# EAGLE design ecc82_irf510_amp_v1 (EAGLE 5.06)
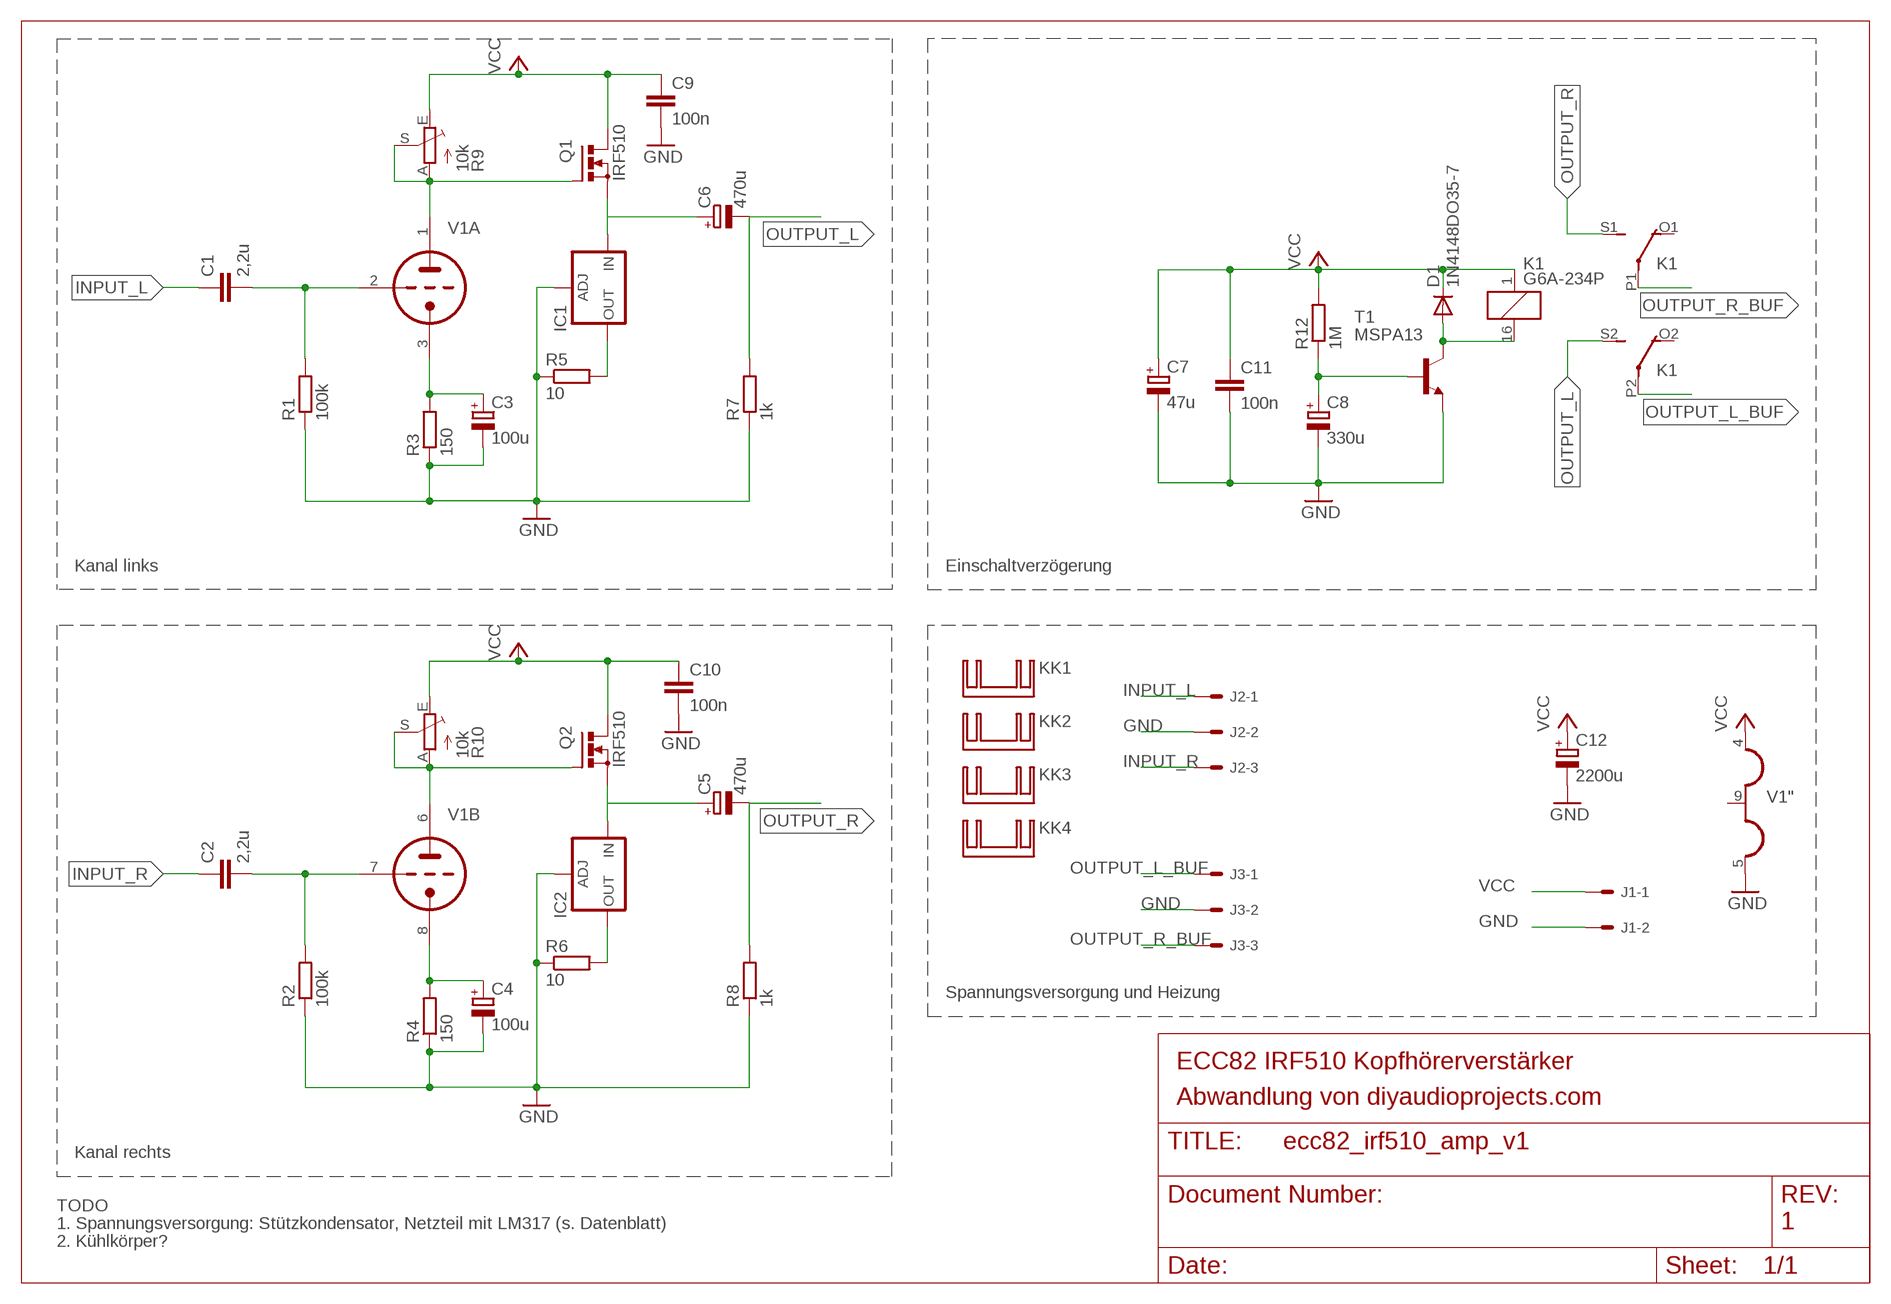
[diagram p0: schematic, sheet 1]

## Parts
C1  2,2u  C10/6  [C10B6]
C2  2,2u  C10/6  [C10B6]
C3  100u  CPOL-EUE5-8.5  [E5-8,5]
C4  100u  CPOL-EUE5-8.5  [E5-8,5]
C5  470u  CPOL-EUE5-10.5  [E5-10,5]
C6  470u  CPOL-EUE5-10.5  [E5-10,5]
C7  47u  CPOL-EUE2-5  [E2-5]
C8  330u  CPOL-EUE5-10.5  [E5-10,5]
C9  100n  C-EUC0805  [C0805]
C10  100n  C-EUC0805  [C0805]
C11  100n  C-EUC0805  [C0805]
C12  2200u  CPOL-EUE5-13  [E5-13]
D1  1N4148DO35-7  [DO35-7]
IC1  LM317TS  [317TS]
IC2  LM317TS  [317TS]
J1  22-27-2021-02  [6410-02]
J2  22-27-2031-03  [6410-03]
J3  22-27-2031-03  [6410-03]
K1  G6A-234P  [G6A-234P]
KK1  D03S  [D03S]
KK2  D03S  [D03S]
KK3  D03S  [D03S]
KK4  D03S  [D03S]
Q1  IRF510  IRF512  [TO220BV]
Q2  IRF510  IRF512  [TO220BV]
R1  100k  R-EU_0207/10  [0207/10]
R2  100k  R-EU_0207/10  [0207/10]
R3  150  R-EU_0207/10  [0207/10]
R4  150  R-EU_0207/10  [0207/10]
R5  10  R-EU_0207/10  [0207/10]
R6  10  R-EU_0207/10  [0207/10]
R7  1k  R-EU_0207/10  [0207/10]
R8  1k  R-EU_0207/10  [0207/10]
R9  10k  TRIM_EU-B64Y  [B64Y]
R10  10k  TRIM_EU-B64Y  [B64Y]
R12  1M  R-EU_0207/10  [0207/10]
T1  MSPA13  MPSA13-NPN-TO92-CBE  [TO92-CBE]
V1  ECC82-P  [NOVAL]

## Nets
GND: C3.- C4.- C7.- C8.- C9.2 C10.2 C11.2 C12.- IC1.1(ADJ) IC2.1(ADJ) J1.2 J2.2 J3.2 R1.1 R2.1 R3.1 R4.1 R5.1 R6.1 R7.1 R8.1 T1.E V1.5(":H3)
INPUT_L: C1.1 J2.1
INPUT_R: C2.1 J2.3
N$1: C1.2 R1.2 V1.2(A:TG)
N$2: C3.+ R3.2 V1.3(A:TK)
N$3: Q1.G R9.A R9.S V1.1(A:TA)
N$4: C2.2 R2.2 V1.7(B:TG)
N$5: C4.+ R4.2 V1.8(B:TK)
N$6: Q2.G R10.A R10.S V1.6(B:TA)
N$7: C6.+ IC1.3(IN) Q1.S
N$8: IC1.2(OUT) R5.2
N$9: C5.+ IC2.3(IN) Q2.S
N$10: IC2.2(OUT) R6.2
N$12: D1.A K1.16 T1.C
N$13: C8.+ R12.1 T1.B
OUTPUT_L: C6.- K1.S2(3:S) R7.2
OUTPUT_L_BUF: J3.1 K1.P2(3:P)
OUTPUT_R: C5.- K1.S1(2:S) R8.2
OUTPUT_R_BUF: J3.3 K1.P1(2:P)
VCC: C7.+ C9.1 C10.1 C11.1 C12.+ D1.C J1.1 K1.1 Q1.D Q2.D R9.E R10.E R12.2 V1.4(":H1)
Unconnected: K1.O1(2:O) K1.O2(3:O) V1.9(":H2)

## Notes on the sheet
- Kanal links | Einschaltverzögerung
- Spannungsversorgung und Heizung
- ECC82 IRF510 Kopfhörerverstärker
- Abwandlung von diyaudioprojects.com
- Kanal rechts
- TODO
- 1. Spannungsversorgung: Stützkondensator, Netzteil mit LM317 (s. Datenblatt) | 1
- 2. Kühlkörper?

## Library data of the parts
C1 C2 = capacitor-wima:C: CAPACITOR
C3-C8 C12 = rcl:CPOL-EU: POLARIZED CAPACITOR, European symbol
C9-C11 = rcl:C-EU: CAPACITOR, European symbol
D1 = diode:1N4148: DIODE
IC1 IC2 = v-reg:LM317TS: VOLTAGE REGULATOR
J1 = con-molex:22-?-02: CONNECTOR
J2 J3 = con-molex:22-?-03: CONNECTOR wire to board 2.54 mm (.1 inch) pitch header
K1 = relay:G6A-234P: RELAY 2 x switch, 0.3 A/125 V AC, 1 A/30 V DC, Omron
KK1-KK4 = heatsink:D03S: HEATSINK
Q1 Q2 = transistor-power:IRF512: N-CHANNEL MOS FET
R1-R8 R12 = rcl:R-EU_: RESISTOR, European symbol
R9 R10 = pot:TRIM_EU-: POTENTIOMETER
T1 = transistor:*-NPN-: NPN Transistror BF959 corrected 2008.03.06
V1 = tubes:ECC82-P

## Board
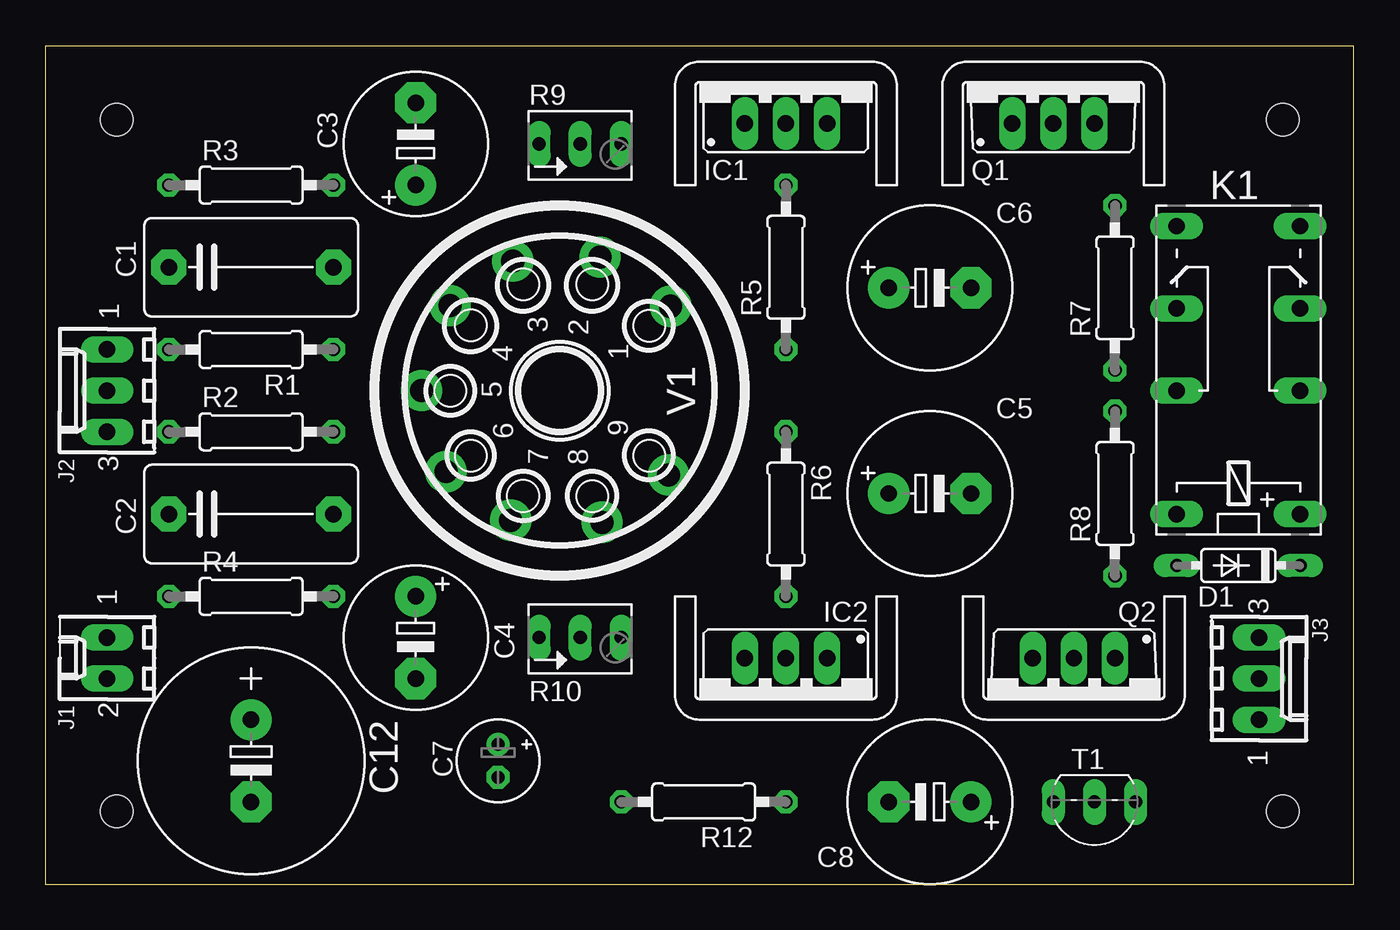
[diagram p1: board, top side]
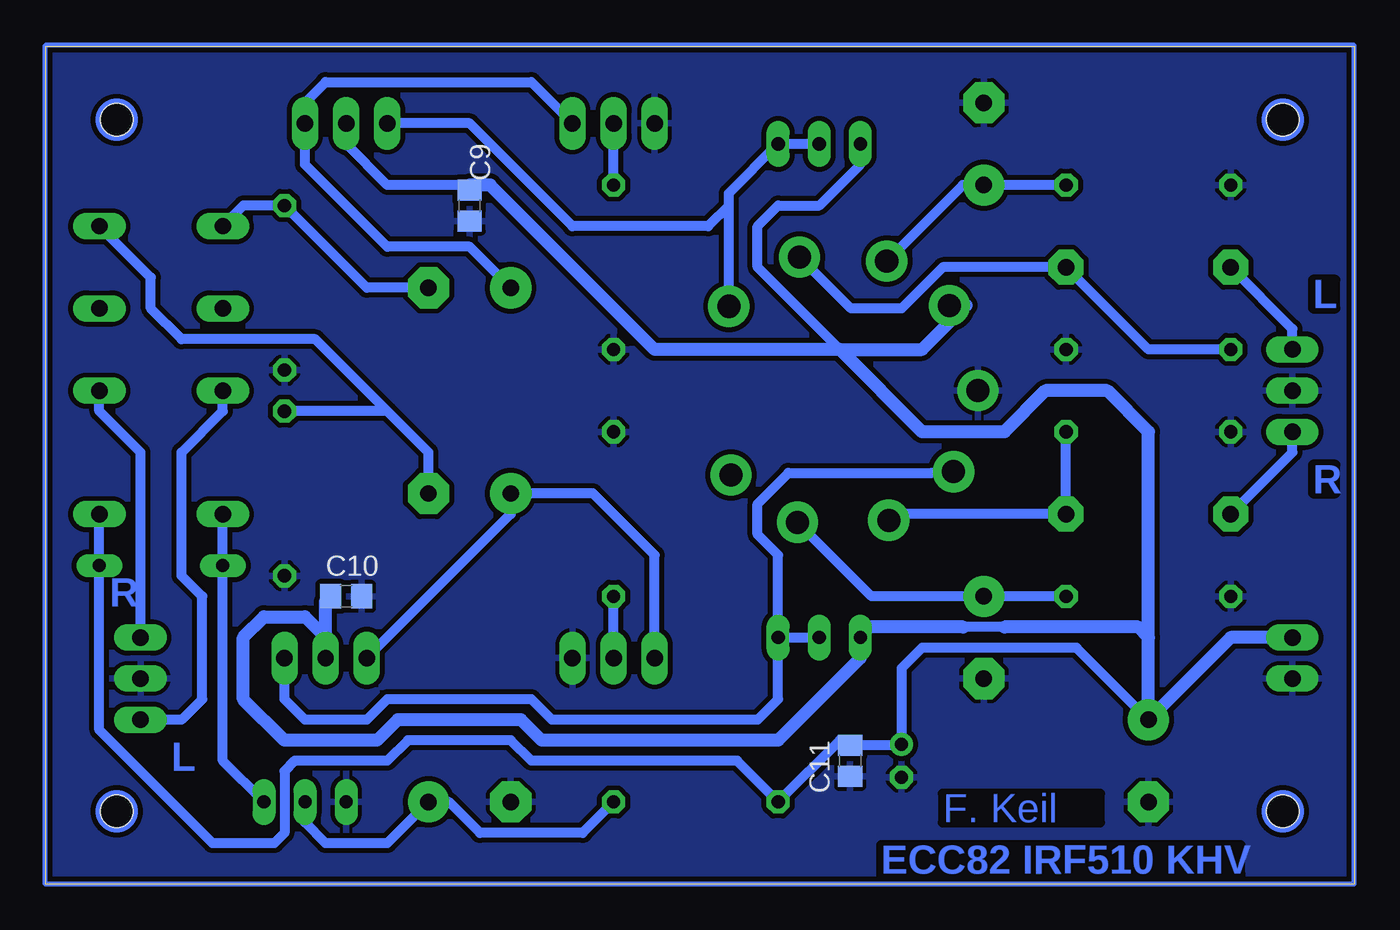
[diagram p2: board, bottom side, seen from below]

Size 80.79 x 51.76 mm. Coordinates in mm from the lower left corner, seen from the top.
Outline: 0,0 80.79,0 80.79,51.76 0,51.76 0,0
Copper layers (1*16): Top 0.035mm / dielectric 1.5mm / Bottom 0.035mm
Design rules "SparkFun *": minimum track width 8mil, minimum drill 20mil, track to track 10mil, track to pad 10mil, pad to pad 10mil, via to via 10mil, smd to smd 10mil, copper to edge 10mil, drill to drill 8mil, minimum pad ring 12mil, minimum via ring 10mil, stop-mask expansion 4mil, vias tented up to drill 25mil, thermal gap 10mil
Holes 2 mm at 4.4,4.5 4.4,47.2 76.4,4.5 76.4,47.2

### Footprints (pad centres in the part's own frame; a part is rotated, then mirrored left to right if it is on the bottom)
C10B6 = drill 1.016 pad 2.159 octagon: 1 -5.08,0; 2 5.08,0
E5-8,5 = drill 1.016 pad 2.54 round: + -2.54,0 | drill 1.016 pad 2.54 octagon: - 2.54,0
E5-10,5 = drill 1.016 pad 2.54 round: + -2.54,0 | drill 1.016 pad 2.54 octagon: - 2.54,0
E2-5 = drill 0.813 pad 1.27 round: + -1.016,0 | drill 0.813 pad 1.27 octagon: - 1.016,0
C0805 = smd 1.3 x 1.5: 1 -0.95,0; 2 0.95,0
E5-13 = drill 1.016 pad 2.54 round: + -2.54,0 | drill 1.016 pad 2.54 octagon: - 2.54,0
DO35-7 = drill 0.813 long: A 3.81,0; C -3.81,0
317TS = drill 1.016 long: 1 -2.54,-2.54; 2 0,-2.54; 3 2.54,-2.54
6410-02 = drill 1.016 long: 1 1.27,0; 2 -1.27,0
6410-03 = drill 1.016 long: 1 2.54,0; 2 0,0; 3 -2.54,0
G6A-234P = drill 1.016 long: 1 -3.81,-3.81; 16 -3.81,3.81; O1 8.89,-3.81; O2 8.89,3.81; P1 3.81,-3.81; P2 3.81,3.81; S1 13.97,-3.81; S2 13.97,3.81
TO220BV = drill 1.016 long: D 0,-2.54; G -2.54,-2.54; S 2.54,-2.54
0207/10 = drill 0.813 octagon: 1 -5.08,0; 2 5.08,0
B64Y = drill 0.813 long: A 2.54,0; E -2.54,0; S 0,0
TO92-CBE = drill 0.813 long: B 0,0; C -2.54,0; E 2.54,0
NOVAL = drill 1.422 pad 2.54 round: 1 5.207,-6.858; 2 8.254,-2.484; 3 8.004,2.893; 4 5.258,6.77; 5 0,8.524; 6 -5.004,7.024; 7 -8.004,3.02; 8 -8.127,-2.611; 9 -5.207,-6.731

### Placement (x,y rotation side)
C1  12.7,38.1 0 top
C2  12.7,22.86 0 top
C3  22.86,45.72 90 top
C4  22.86,15.24 270 top
C5  54.61,24.13 0 top
C6  54.61,36.83 0 top
C7  27.94,7.62 270 top
C8  54.61,5.08 180 top
C9  54.61,41.91 270 bottom
C10  62.23,17.78 0 bottom
C11  31.11,7.62 270 bottom
C12  12.7,7.62 270 top
D1  73.66,19.68 180 top
IC1  45.72,49.53 0 top
IC2  45.72,11.43 180 top
J1  3.81,13.97 90 top
J2  3.81,30.48 90 top
J3  74.93,12.7 270 top
K1  73.66,26.67 90 top
KK1  63.5,11.43 0 top
KK2  45.72,11.43 0 top
KK3  45.72,49.53 180 top
KK4  62.23,49.53 180 top
Q1  62.23,49.53 0 top
Q2  63.5,11.43 180 top
R1  12.7,33.02 180 top
R2  12.7,27.94 0 top
R3  12.7,43.18 0 top
R4  12.7,17.78 0 top
R5  45.72,38.1 90 top
R6  45.72,22.86 270 top
R7  66.04,36.83 90 top
R8  66.04,24.13 90 top
R9  33.02,45.72 0 top
R10  33.02,15.24 0 top
R12  40.64,5.08 180 top
T1  64.77,5.08 180 top
V1  31.75,30.48 90 top

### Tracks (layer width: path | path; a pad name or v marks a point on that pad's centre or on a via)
GND
  pour Bottom (isolate 0.305): 0,52.07 80.64,52.07 80.64,0 0,0
INPUT_L
  Bottom 0.61: J2.1 3.81,34.29 C1.1
INPUT_R
  Bottom 0.61: J2.3 3.81,26.67 C2.1
N$1
  Bottom 0.61: R1.2 12.7,33.02 C1.2 25.4,38.1 27.94,35.56 31.06,35.56 V1.2
N$2
  Bottom 0.61: R3.2 C3.+ 24.16,43.18 V1.3
N$3
  Bottom 0.61: R9.S R9.A 38.61,42.67 38.61,41.91 | V1.1 38.61,41.91 | Q1.G 54.61,46.99 48.26,40.64 39.88,40.64 38.61,41.91
N$4
  Bottom 0.61: V1.7 28.35,22.86 C2.2 R2.2
N$5
  Bottom 0.61: V1.8 29.79,17.78 C4.+ R4.2
N$6
  Bottom 0.61: R10.A R10.S | Q2.G 66.04,11.43 64.77,10.16 60.96,10.16 59.69,11.43 50.8,11.43 49.53,10.16 36.83,10.16 35.56,11.43 R10.A | R10.A 35.56,20.32 36.83,21.59 36.83,23.5 34.92,25.4 26.07,25.4 V1.6
N$7
  Bottom 0.61: C6.+ 54.61,39.37 59.69,39.37 64.77,44.45 Q1.S 64.77,48.26 63.5,49.53 50.8,49.53 IC1.3
N$8
  Bottom 0.61: R5.2 IC1.2
N$9
  Bottom 0.61: IC2.3 43.18,20.32 46.99,24.13 C5.+ 52.07,22.86 Q2.S
N$10
  Bottom 0.61: IC2.2 R6.2
N$11
  Bottom 0.305: 0,51.8 80.8,51.8 80.8,0 0,0 0,51.8
N$12
  Bottom 0.61: K1.16 D1.A 69.85,7.62 T1.C
N$13
  Bottom 0.61: R12.1 47.62,3.17 53.98,3.17 55.88,5.08 C8.+ 59.69,2.54 63.5,2.54 64.77,3.81 T1.B
OUTPUT_L
  Bottom 0.61: C6.- 60.96,36.83 R7.2 68.58,41.91 K1.S2
OUTPUT_L_BUF
  Bottom 0.61: K1.P2 69.85,29.21 72.39,26.67 72.39,19.05 71.12,17.78 71.12,11.43 72.39,10.16 J3.1
OUTPUT_R
  Bottom 0.61: K1.S1 74.3,37.47 74.3,35.56 72.39,33.66 64.14,33.66 59.69,29.21 | C5.- 57.15,26.67 59.69,29.21 | 59.69,29.21 R8.2
OUTPUT_R_BUF
  Bottom 0.61: K1.P1 77.47,29.21 74.93,26.67 J3.3
VCC
  Bottom 0.61: R9.E 30.48,44.45 33.02,41.91 35.56,41.91 36.83,40.64 36.83,38.1 31.75,33.02 | K1.1 D1.C 77.47,9.53 70.48,2.54 66.67,2.54 66.04,3.17 66.04,6.99 65.41,7.62 59.69,7.62 58.42,8.89 52.07,8.89 50.8,7.62 38.1,7.62 R12.2 31.75,8.89 31.43,8.89 C11.1 28.01,8.57 C7.+ 27.94,13.34 26.67,14.61 17.14,14.61 C12.+ | 54.61,43.18 59.69,43.18 62.23,45.72 | 21.59,15.88 24.13,15.88
  Bottom 0.813: 31.75,33.02 26.67,33.02 23.95,35.74 V1.4 | 62.23,45.72 Q1.D | 31.75,33.02 26.67,27.94 21.59,27.94 19.05,30.48 15.24,30.48 12.7,27.94 12.7,15.24 | 31.75,33.02 43.18,33.02 53.34,43.18 54.61,43.18 C9.1 | 12.7,15.24 C12.+ 7.62,15.24 J1.1 | 63.5,15.24 64.77,16.51 67.31,16.51 68.58,15.24 68.58,11.43 66.04,8.89 60.33,8.89 59.05,10.16 51.44,10.16 50.16,8.89 35.56,8.89 30.48,13.97 R10.E 30.48,15.88 24.13,15.88 | 63.5,15.24 Q2.D | 63.5,15.24 63.5,17.46 C10.1 | 21.59,15.88 13.34,15.88 12.7,15.24
(copper drawn outside any net)
  shapes: Bottom circle x4

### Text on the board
Bottom: L | R | R | L | F. Keil | ECC82 IRF510 KHV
